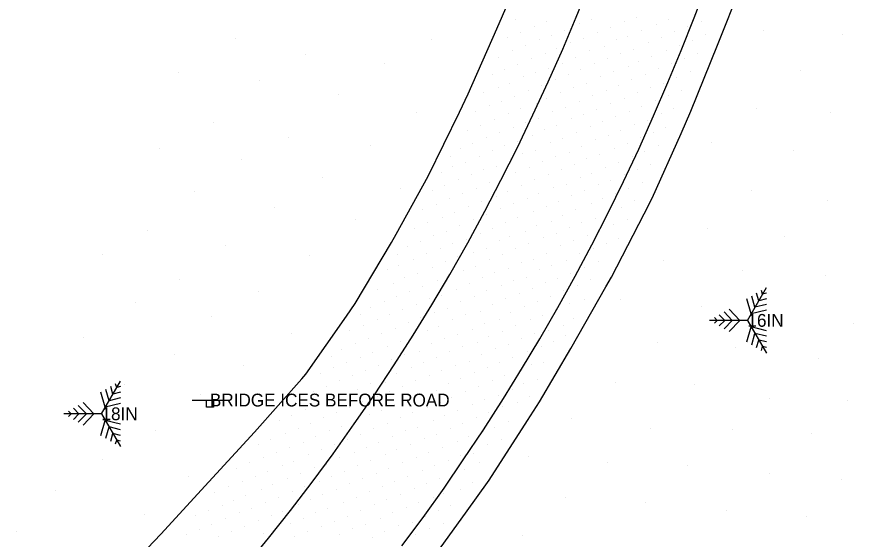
# Model space of a CAD drawing. Extents: x 1732346 to 1733076, y 467730 to 468633.
# Drawn here: x 1732514.8 to 1732632.7, y 468330.7 to 468404.1 of the extents above; entities that cross this region are included whole.
import ezdxf

# ---------------------------------------------------------------- set-up
doc = ezdxf.new("R2010")
doc.units = 0
for name, color, linetype in [('Default', 7, 'Continuous'), ('S_Ground_SpotElevation', 7, 'Continuous'), ('S_Roadway_Edge_Pavement', 7, 'Continuous'), ('S_Roadway_Painted_Lines', 7, 'Continuous'), ('S_Text', 7, 'Continuous'), ('S_Traffic_Sign_SinglePost', 7, 'Continuous'), ('S_Trees_Conifer_Pay', 7, 'Continuous')]:
    doc.layers.add(name, color=color, linetype=linetype)

# ---------------------------------------------------------------- blocks, each defined once
blk = doc.blocks.new('POINT_DISPLAY')
at = {"layer": 'Default'}
blk.add_line((0, 0), (0, 0), dxfattribs=at)

msp = doc.modelspace()

# ---------------------------------------------------------------- linework, layer by layer
at = {"layer": 'S_Roadway_Edge_Pavement'}
for points in [[(1732572.05, 468326.23), (1732577.91, 468334.33), (1732581.24, 468338.95), (1732586.63, 468347.37), (1732588.3, 468349.98), (1732592.71, 468357.46), (1732597.64, 468366.15), (1732598.42, 468367.53), (1732603.01, 468376.41), (1732604.14, 468378.61), (1732608.2, 468387.74), (1732609.59, 468390.87), (1732613.3, 468400.15), (1732616.65, 468408.55), (1732619.8, 468418.04), (1732621.97, 468424.57), (1732624.79, 468434.17), (1732627.07, 468441.93), (1732629.39, 468451.66), (1732630.3, 468455.46), (1732630.47, 468455.69), (1732632.18, 468465.54), (1732632.53, 468467.53), (1732633.87, 468477.44)], [(1732528.46, 468324.42), (1732535.06, 468331.36), (1732541.83, 468338.72), (1732548.25, 468345.7), (1732554.86, 468353.2), (1732555.43, 468353.85), (1732561.15, 468362.05), (1732562.37, 468363.81), (1732567.49, 468372.4), (1732568.16, 468373.54), (1732572.66, 468381.72), (1732577.04, 468390.71), (1732578.29, 468393.28), (1732582.29, 468402.45), (1732585.49, 468409.8)]]:
    msp.add_lwpolyline(points, dxfattribs=at)
at = {"layer": 'S_Roadway_Painted_Lines'}
for points in [[(1732547.02, 468326.92), (1732550.21, 468330.8), (1732553.3, 468334.72), (1732556.33, 468338.7), (1732559.29, 468342.69), (1732562.26, 468346.87), (1732565.09, 468350.99), (1732567.86, 468355.17), (1732570.53, 468359.36), (1732573.15, 468363.62), (1732575.67, 468367.87), (1732578.22, 468372.34), (1732580.62, 468376.82), (1732582.86, 468381.18), (1732585.19, 468385.77), (1732587.38, 468390.33), (1732589.53, 468394.98), (1732591.56, 468399.57), (1732593.46, 468404.1), (1732595.35, 468408.81)], [(1732568.94, 468329.72), (1732571.94, 468333.7), (1732574.88, 468337.82), (1732577.58, 468341.83), (1732580.42, 468346.04), (1732583.25, 468350.46), (1732585.78, 468354.58), (1732588.32, 468358.82), (1732590.88, 468363.26), (1732593.3, 468367.67), (1732595.65, 468372.08), (1732597.94, 468376.55), (1732600.12, 468380.97), (1732602.24, 468385.51), (1732604.34, 468390.2), (1732606.35, 468394.89), (1732608.21, 468399.41), (1732610.02, 468404), (1732611.86, 468408.79)]]:
    msp.add_lwpolyline(points, dxfattribs=at)
at = {"layer": 'S_Traffic_Sign_SinglePost'}
msp.add_line((1732539.47, 468350.23), (1732544.46, 468350.23), dxfattribs=at)
msp.add_lwpolyline([(1732541.46, 468350.23), (1732542.46, 468350.23), (1732542.46, 468349.23), (1732541.46, 468349.23)], close=True, dxfattribs=at)
at = {"layer": 'S_Trees_Conifer_Pay'}
for p, q in [((1732617.53, 468361.44), (1732620.19, 468366.05)), ((1732618.59, 468363.28), (1732618.14, 468364.86)), ((1732619.12, 468364.21), (1732618.82, 468365.26)), ((1732619.66, 468365.13), (1732619.5, 468365.66)), ((1732620.19, 468365.26), (1732619.66, 468365.13)), ((1732618.06, 468362.36), (1732617.45, 468364.47)), ((1732620.19, 468363.68), (1732618.59, 468363.28)), ((1732620.19, 468364.47), (1732619.12, 468364.21)), ((1732615.4, 468361.44), (1732614.26, 468362.63)), ((1732616.46, 468361.44), (1732614.94, 468363.02)), ((1732620.19, 468362.89), (1732618.06, 468362.36)), ((1732617.53, 468361.44), (1732612.2, 468361.44)), ((1732613.27, 468361.44), (1732612.89, 468361.84)), ((1732612.89, 468361.05), (1732613.27, 468361.44)), ((1732614.33, 468361.44), (1732613.57, 468362.23)), ((1732613.57, 468360.65), (1732614.33, 468361.44)), ((1732614.26, 468360.25), (1732615.4, 468361.44)), ((1732614.94, 468359.86), (1732616.46, 468361.44)), ((1732617.53, 468361.44), (1732620.19, 468356.83)), ((1732617.45, 468358.41), (1732618.06, 468360.52)), ((1732620.19, 468359.99), (1732618.06, 468360.52)), ((1732618.14, 468358.02), (1732618.59, 468359.59)), ((1732620.19, 468359.2), (1732618.59, 468359.59)), ((1732618.82, 468357.62), (1732619.12, 468358.67)), ((1732620.19, 468358.41), (1732619.12, 468358.67)), ((1732619.5, 468357.22), (1732619.66, 468357.75)), ((1732620.19, 468357.62), (1732619.66, 468357.75)), ((1732526.72, 468348.3), (1732529.38, 468352.91)), ((1732528.31, 468351.06), (1732528.01, 468352.12)), ((1732528.85, 468351.98), (1732528.7, 468352.51)), ((1732529.38, 468352.12), (1732528.85, 468351.98)), ((1732527.25, 468349.22), (1732526.64, 468351.33)), ((1732527.79, 468350.14), (1732527.33, 468351.72)), ((1732529.38, 468351.33), (1732528.31, 468351.06)), ((1732524.59, 468348.3), (1732523.45, 468349.48)), ((1732525.65, 468348.3), (1732524.13, 468349.88)), ((1732529.38, 468349.74), (1732527.25, 468349.22)), ((1732529.38, 468350.54), (1732527.79, 468350.14)), ((1732526.72, 468348.3), (1732521.4, 468348.3)), ((1732522.46, 468348.3), (1732522.08, 468348.69)), ((1732522.08, 468347.9), (1732522.46, 468348.3)), ((1732523.53, 468348.3), (1732522.77, 468349.09)), ((1732522.77, 468347.51), (1732523.53, 468348.3)), ((1732523.45, 468347.11), (1732524.59, 468348.3)), ((1732524.13, 468346.72), (1732525.65, 468348.3)), ((1732526.72, 468348.3), (1732529.38, 468343.69)), ((1732526.64, 468345.27), (1732527.25, 468347.37)), ((1732529.38, 468346.85), (1732527.25, 468347.37)), ((1732527.33, 468344.87), (1732527.79, 468346.45)), ((1732529.38, 468346.06), (1732527.79, 468346.45)), ((1732528.01, 468344.47), (1732528.31, 468345.53)), ((1732529.38, 468345.27), (1732528.31, 468345.53)), ((1732528.7, 468344.08), (1732528.85, 468344.61)), ((1732529.38, 468344.47), (1732528.85, 468344.61))]:
    msp.add_line(p, q, dxfattribs=at)

# ---------------------------------------------------------------- block references
at = {"layer": 'S_Ground_SpotElevation'}
for p in [(1732584.87, 468403.81), (1732595.67, 468403.7), (1732601.95, 468404.09), (1732606.37, 468403.77), (1732587.59, 468402.72), (1732589.34, 468403.46), (1732593.87, 468403.14), (1732598.25, 468402.63), (1732600.19, 468403.48), (1732604.69, 468403.11), (1732609.13, 468402.78), (1732611.03, 468403.42), (1732585.58, 468401.87), (1732589.96, 468401.45), (1732591.82, 468402.24), (1732596.39, 468401.99), (1732600.7, 468401.34), (1732602.59, 468402.22), (1732605.41, 468401.29), (1732607.24, 468402.01), (1732611.66, 468401.6), (1732619.72, 468402.27), (1732630.88, 468401.67), (1732545.54, 468401.12), (1732573.05, 468400.91), (1732583.8, 468401.19), (1732588.35, 468400.9), (1732592.7, 468400.51), (1732594.46, 468401.05), (1732599.06, 468400.91), (1732603.63, 468400.57), (1732607.96, 468400.14), (1732609.86, 468400.79), (1732584.56, 468399.33), (1732586.34, 468400.05), (1732589.18, 468399), (1732590.72, 468399.64), (1732595.32, 468399.39), (1732597.44, 468399.97), (1732599.73, 468398.92), (1732601.51, 468399.48), (1732606.15, 468399.44), (1732610.56, 468398.96), (1732555.44, 468398.81), (1732582.56, 468398.4), (1732587.19, 468398.3), (1732593.42, 468398.4), (1732597.92, 468398.3), (1732602.25, 468397.84), (1732604.07, 468398.5), (1732608.71, 468398.32), (1732566.47, 468397.6), (1732583.35, 468396.7), (1732585.2, 468397.42), (1732589.61, 468396.88), (1732591.49, 468397.6), (1732594.11, 468396.72), (1732596.09, 468397.53), (1732600.77, 468397.13), (1732604.99, 468396.8), (1732606.89, 468397.59), (1732624.98, 468396.63), (1732537.6, 468396.3), (1732581.7, 468396.02), (1732586.02, 468395.67), (1732587.79, 468396.31), (1732592.38, 468396.04), (1732596.92, 468395.7), (1732598.74, 468396.37), (1732603.15, 468396.05), (1732607.52, 468395.6), (1732609.49, 468396.46), (1732548.97, 468395.15), (1732582.53, 468394.22), (1732584.11, 468394.82), (1732588.64, 468394.54), (1732590.59, 468395.31), (1732594.86, 468394.75), (1732599.39, 468394.43), (1732601.21, 468395.27), (1732603.91, 468394.23), (1732605.69, 468394.75), (1732560.06, 468393.14), (1732580.46, 468393.43), (1732586.81, 468393.75), (1732591.25, 468393.44), (1732593.02, 468394.16), (1732595.78, 468393.11), (1732597.75, 468393.83), (1732602.02, 468393.46), (1732606.43, 468393.08), (1732608.19, 468393.71), (1732583.02, 468392.28), (1732584.8, 468392.92), (1732587.82, 468391.96), (1732589.28, 468392.63), (1732593.86, 468392.27), (1732598.22, 468391.9), (1732600.19, 468392.63), (1732604.61, 468392.37), (1732571.06, 468390.67), (1732579.36, 468390.76), (1732581.31, 468391.59), (1732585.66, 468391.2), (1732590.07, 468390.78), (1732591.9, 468391.32), (1732596.27, 468391.07), (1732600.96, 468390.78), (1732602.59, 468391.47), (1732607.2, 468391.23), (1732618.87, 468391.25), (1732582.03, 468389.7), (1732583.94, 468390.51), (1732588.12, 468389.8), (1732592.79, 468389.77), (1732594.46, 468390.34), (1732599.05, 468390.09), (1732603.41, 468389.55), (1732605.5, 468390.48), (1732629.23, 468390.62), (1732542.51, 468389.23), (1732580.01, 468388.87), (1732584.67, 468388.52), (1732586.3, 468389.27), (1732590.72, 468388.84), (1732595.41, 468388.67), (1732597.22, 468389.39), (1732601.66, 468388.97), (1732606.07, 468388.61), (1732553.04, 468387.14), (1732578.17, 468388.15), (1732582.72, 468387.85), (1732587.37, 468387.46), (1732589.02, 468388.22), (1732593.49, 468387.81), (1732598.03, 468387.44), (1732599.73, 468388.13), (1732602.43, 468387.18), (1732604.36, 468387.92), (1732564.47, 468385.99), (1732578.93, 468386.35), (1732580.83, 468387.09), (1732583.42, 468385.98), (1732585.24, 468386.57), (1732589.84, 468386.4), (1732591.59, 468387.06), (1732594.18, 468385.96), (1732596.16, 468386.81), (1732600.6, 468386.36), (1732604.96, 468385.98), (1732612.51, 468386.44), (1732534.91, 468385.59), (1732577.21, 468385.67), (1732581.62, 468385.28), (1732585.97, 468384.85), (1732587.71, 468385.36), (1732592.47, 468385.1), (1732596.71, 468384.79), (1732598.78, 468385.67), (1732603.07, 468385.14), (1732623.95, 468385.36), (1732546.42, 468384.12), (1732575.73, 468384.52), (1732577.83, 468383.71), (1732579.82, 468384.55), (1732584.17, 468384.14), (1732588.71, 468383.75), (1732590.59, 468384.53), (1732594.97, 468384.17), (1732599.34, 468383.7), (1732601.34, 468384.54), (1732576.03, 468383.04), (1732580.48, 468382.67), (1732582.23, 468383.14), (1732586.82, 468382.99), (1732591.38, 468382.71), (1732593.22, 468383.3), (1732597.61, 468382.97), (1732602.03, 468382.66), (1732603.86, 468383.4), (1732557.77, 468381.59), (1732574.56, 468382.17), (1732578.68, 468381.93), (1732583.05, 468381.44), (1732584.88, 468382.21), (1732587.65, 468381.22), (1732589.57, 468381.96), (1732594.04, 468381.58), (1732595.54, 468382.14), (1732600.19, 468381.94), (1732574.91, 468380.44), (1732576.9, 468381.2), (1732581.2, 468380.8), (1732585.72, 468380.47), (1732590.26, 468380.12), (1732592.06, 468380.56), (1732596.58, 468380.5), (1732598.33, 468381.17), (1732602.71, 468380.77), (1732539.85, 468379.53), (1732568.76, 468379.98), (1732573.28, 468379.66), (1732577.45, 468379.24), (1732579.37, 468379.96), (1732582.25, 468378.92), (1732583.78, 468379.57), (1732588.2, 468379.29), (1732592.76, 468378.97), (1732594.57, 468379.71), (1732598.99, 468379.24), (1732600.81, 468380.02), (1732618.06, 468379.7), (1732573.88, 468377.76), (1732575.64, 468378.55), (1732580.13, 468378.2), (1732584.65, 468377.85), (1732586.54, 468378.61), (1732590.98, 468378.17), (1732595.66, 468377.84), (1732597.19, 468378.61), (1732601.63, 468378.23), (1732628.76, 468378.25), (1732550.99, 468377.34), (1732571.82, 468376.97), (1732576.29, 468376.59), (1732578.28, 468377.48), (1732582.85, 468377.14), (1732587.49, 468376.7), (1732589.33, 468377.41), (1732593.42, 468377.06), (1732597.86, 468376.56), (1732599.82, 468377.31), (1732562.48, 468375.61), (1732574.68, 468375.97), (1732579.06, 468375.62), (1732580.83, 468376.33), (1732585.23, 468375.94), (1732590, 468375.4), (1732591.57, 468376.25), (1732596.18, 468375.77), (1732600.68, 468375.57), (1732570.77, 468374.4), (1732572.61, 468375.17), (1732577.01, 468374.73), (1732581.62, 468374.29), (1732583.53, 468375.16), (1732587.85, 468374.74), (1732592.46, 468374.54), (1732594.2, 468375.22), (1732598.67, 468374.86), (1732611.88, 468374.39), (1732533.18, 468374.04), (1732573.4, 468373.36), (1732575.19, 468373.99), (1732579.97, 468373.61), (1732584.11, 468373.22), (1732586.38, 468373.94), (1732588.82, 468373.06), (1732590.67, 468373.69), (1732595.05, 468373.37), (1732596.68, 468373.89), (1732599.46, 468372.96), (1732622.81, 468373.18), (1732544.12, 468371.92), (1732569.78, 468371.8), (1732571.55, 468372.58), (1732576.08, 468372.28), (1732578.05, 468372.86), (1732582.64, 468372.61), (1732586.7, 468372.19), (1732591.31, 468371.92), (1732593.04, 468372.61), (1732597.69, 468372.28), (1732526.85, 468370.73), (1732568.29, 468370.68), (1732572.43, 468370.79), (1732574.31, 468371.56), (1732578.96, 468371), (1732580.87, 468371.6), (1732583.14, 468370.73), (1732584.89, 468371.49), (1732589.31, 468370.8), (1732593.97, 468370.83), (1732595.89, 468371.54), (1732555.98, 468370.57), (1732570.64, 468370.03), (1732575.01, 468369.69), (1732576.8, 468370.4), (1732581.32, 468370.04), (1732585.75, 468369.61), (1732587.42, 468369.99), (1732592.15, 468369.88), (1732596.63, 468369.66), (1732605.68, 468369.89), (1732566.97, 468368.55), (1732568.52, 468369.18), (1732573.22, 468368.94), (1732577.65, 468368.43), (1732579.23, 468368.96), (1732583.96, 468368.68), (1732588.34, 468368.58), (1732589.99, 468369.13), (1732594.69, 468368.94), (1732616.79, 468368.49), (1732537.66, 468367.24), (1732569.36, 468367.4), (1732571.21, 468368.09), (1732573.89, 468367.07), (1732575.56, 468367.53), (1732580.22, 468367.45), (1732581.96, 468368.18), (1732586.47, 468367.45), (1732590.77, 468367.3), (1732592.6, 468368.06), (1732595.53, 468367.13), (1732628.48, 468367.81), (1732567.71, 468366.69), (1732571.87, 468366.22), (1732578.4, 468366.65), (1732582.99, 468366.31), (1732584.65, 468367.02), (1732587.29, 468365.99), (1732589.11, 468366.74), (1732593.62, 468366.36), (1732548.78, 468365.44), (1732565.56, 468365.82), (1732568.21, 468364.81), (1732570.03, 468365.45), (1732574.49, 468364.99), (1732576.62, 468365.76), (1732579.21, 468364.81), (1732580.9, 468365.57), (1732585.42, 468365.22), (1732589.84, 468364.86), (1732591.73, 468365.63), (1732531.5, 468363.9), (1732566.57, 468364.12), (1732570.99, 468363.71), (1732572.83, 468364.5), (1732577.15, 468364.08), (1732581.65, 468363.71), (1732583.5, 468364.48), (1732588.04, 468364.14), (1732592.45, 468363.76), (1732594.65, 468364.36), (1732599.71, 468364.42), (1732564.55, 468363.29), (1732569.08, 468362.94), (1732573.55, 468362.55), (1732575.4, 468363.07), (1732580.06, 468362.73), (1732584.17, 468362.59), (1732586.24, 468363.38), (1732590.53, 468362.99), (1732611.1, 468363.39), (1732542.14, 468361.98), (1732563.11, 468362.21), (1732565.46, 468361.5), (1732567.18, 468362.24), (1732571.61, 468361.85), (1732576.1, 468361.52), (1732577.9, 468362.24), (1732582.61, 468361.6), (1732586.97, 468361.55), (1732588.69, 468362.13), (1732593.04, 468361.76), (1732622.37, 468362.32), (1732563.5, 468360.71), (1732568.03, 468360.36), (1732569.92, 468361.14), (1732572.49, 468360.01), (1732574.1, 468360.63), (1732578.91, 468360.11), (1732580.56, 468361.03), (1732584.92, 468360.69), (1732589.54, 468360), (1732591.69, 468360.74), (1732632.44, 468360.99), (1732524.24, 468358.99), (1732553.41, 468359.53), (1732561.54, 468359.97), (1732564.28, 468358.9), (1732566.15, 468359.65), (1732570.43, 468359.23), (1732574.95, 468358.89), (1732576.72, 468359.49), (1732581.17, 468359.22), (1732583.15, 468359.86), (1732585.75, 468358.9), (1732587.64, 468359.58), (1732591.99, 468359.25), (1732562.43, 468358.13), (1732566.88, 468357.73), (1732568.75, 468358.51), (1732573.13, 468358.15), (1732577.51, 468357.71), (1732579.58, 468358.34), (1732583.92, 468358.11), (1732588.64, 468357.77), (1732590.2, 468358.42), (1732604.95, 468358.28), (1732615.88, 468357.67), (1732537.04, 468356.67), (1732560.52, 468357.39), (1732564.86, 468356.98), (1732569.35, 468356.63), (1732571.42, 468357.05), (1732575.64, 468357.01), (1732580.09, 468356.62), (1732582.11, 468357.43), (1732586.6, 468357.06), (1732559.07, 468356.37), (1732561.18, 468355.49), (1732563.11, 468356.24), (1732567.46, 468355.88), (1732572.05, 468355.52), (1732573.78, 468356.25), (1732578.41, 468355.68), (1732582.69, 468355.53), (1732584.54, 468356.19), (1732588.9, 468355.55), (1732627.46, 468356.13), (1732546.64, 468355.04), (1732559.37, 468354.79), (1732563.87, 468354.43), (1732565.66, 468355.14), (1732570.31, 468354.83), (1732574.53, 468354.39), (1732576.54, 468355.12), (1732579.16, 468354.11), (1732580.97, 468354.84), (1732585.44, 468354.45), (1732587.19, 468355.2), (1732557.56, 468353.95), (1732560.14, 468352.95), (1732561.94, 468353.63), (1732568.18, 468353.98), (1732570.93, 468352.93), (1732572.88, 468353.72), (1732577.17, 468353.29), (1732581.69, 468352.94), (1732583.43, 468353.68), (1732588.06, 468353.12), (1732529.91, 468352.41), (1732558.37, 468352.17), (1732562.76, 468351.78), (1732564.57, 468352.51), (1732566.63, 468352.74), (1732568.99, 468352.17), (1732575.54, 468352.55), (1732579.73, 468352.14), (1732584.5, 468351.78), (1732586.05, 468352.57), (1732598.93, 468352.69), (1732610.15, 468352.4), (1732540.57, 468351.07), (1732554.66, 468350.61), (1732556.46, 468351.41), (1732560.86, 468351.06), (1732565.45, 468350.72), (1732567.19, 468351.45), (1732571.74, 468351.11), (1732573.77, 468351.51), (1732575.99, 468350.65), (1732577.89, 468351.43), (1732582.48, 468350.91), (1732586.92, 468350.73), (1732557.38, 468349.6), (1732559.1, 468350.3), (1732563.45, 468349.97), (1732567.89, 468349.59), (1732569.7, 468350.3), (1732574.38, 468349.95), (1732578.85, 468349.57), (1732580.62, 468350.37), (1732585.24, 468349.89), (1732620.7, 468350.45), (1732631.56, 468350.13), (1732555.42, 468348.87), (1732559.82, 468348.44), (1732561.6, 468349.22), (1732566.02, 468348.82), (1732570.51, 468348.48), (1732572.52, 468349.18), (1732576.78, 468348.82), (1732581.18, 468348.42), (1732583.15, 468349.26), (1732523.08, 468347.58), (1732551.68, 468347.3), (1732553.46, 468348.11), (1732557.97, 468347.74), (1732564.33, 468348.14), (1732568.77, 468347.75), (1732573.33, 468347.39), (1732574.87, 468348.05), (1732579.47, 468347.75), (1732583.87, 468347.2), (1732592.8, 468347.69), (1732534.31, 468345.89), (1732554.36, 468346.25), (1732556.11, 468346.99), (1732558.79, 468345.9), (1732560.43, 468346.58), (1732562.32, 468346.92), (1732564.97, 468346.24), (1732566.92, 468347), (1732569.44, 468345.89), (1732571.19, 468346.4), (1732575.81, 468346.3), (1732577.53, 468346.97), (1732581.99, 468346.35), (1732603.85, 468346.3), (1732615.41, 468346.03), (1732550.49, 468344.72), (1732552.54, 468345.5), (1732556.81, 468345.11), (1732561.29, 468344.71), (1732563.16, 468345.4), (1732567.58, 468345.16), (1732572.15, 468344.8), (1732573.85, 468345.38), (1732578.27, 468345.12), (1732580.46, 468345.8), (1732582.91, 468344.72), (1732626.59, 468345.47), (1732548.79, 468343.94), (1732553.09, 468343.59), (1732555.18, 468344.33), (1732559.49, 468344.05), (1732563.98, 468343.61), (1732565.6, 468344.25), (1732570.14, 468343.99), (1732574.65, 468343.62), (1732576.71, 468344.4), (1732581.02, 468343.99), (1732551.32, 468342.9), (1732555.81, 468342.55), (1732557.6, 468343.28), (1732562.26, 468342.89), (1732566.59, 468342.57), (1732568.25, 468343.27), (1732572.74, 468342.89), (1732577.19, 468342.48), (1732579.08, 468342.72), (1732526.89, 468341.82), (1732547.53, 468341.4), (1732549.48, 468342.17), (1732553.65, 468341.64), (1732560.21, 468342.16), (1732564.55, 468341.75), (1732569.04, 468341.4), (1732571.06, 468342.17), (1732575.5, 468341.76), (1732579.89, 468341.45), (1732586.71, 468342.3), (1732597.9, 468341.47), (1732545.75, 468340.64), (1732549.99, 468340.23), (1732552.21, 468341.02), (1732556.61, 468340.69), (1732558.39, 468341.12), (1732560.81, 468340.25), (1732562.74, 468341.05), (1732567.11, 468340.64), (1732571.86, 468340.33), (1732573.54, 468341.09), (1732577.81, 468340.42), (1732609.08, 468340.96), (1732538.97, 468339.44), (1732546.54, 468338.8), (1732548.37, 468339.55), (1732552.84, 468339.16), (1732554.71, 468339.94), (1732557.4, 468338.83), (1732559, 468339.52), (1732563.46, 468339.2), (1732565.37, 468339.87), (1732569.71, 468339.53), (1732574.25, 468339.19), (1732576.17, 468339.65), (1732620.61, 468339.84), (1732630.78, 468339.06), (1732544.6, 468338.04), (1732549.18, 468337.7), (1732550.82, 468338.41), (1732555.26, 468338.05), (1732559.81, 468337.7), (1732561.64, 468338.45), (1732566.2, 468338.11), (1732567.97, 468338.77), (1732570.73, 468337.74), (1732572.4, 468338.47), (1732577.2, 468337.72), (1732578.92, 468338.65), (1732520.25, 468337.48), (1732542.59, 468337.23), (1732547.02, 468336.84), (1732551.55, 468336.55), (1732553.58, 468337.33), (1732557.85, 468336.92), (1732562.59, 468336.59), (1732564.44, 468337.35), (1732568.82, 468337.01), (1732573.39, 468336.46), (1732574.79, 468337.15), (1732591.98, 468336.51), (1732543.67, 468335.45), (1732545.28, 468336.13), (1732549.78, 468335.8), (1732554.43, 468335.48), (1732556.13, 468336.24), (1732560.75, 468335.85), (1732565.04, 468335.51), (1732566.84, 468336.19), (1732571.31, 468335.77), (1732575.84, 468335.45), (1732603.2, 468335.82), (1732532.71, 468334.18), (1732541.73, 468334.7), (1732546.13, 468334.35), (1732547.8, 468335.05), (1732552.19, 468334.62), (1732556.8, 468334.37), (1732558.54, 468335.03), (1732563.18, 468334.72), (1732567.69, 468334.41), (1732569.61, 468335.13), (1732574.09, 468334.69), (1732614.54, 468334.68), (1732539.93, 468333.99), (1732544.2, 468333.59), (1732548.84, 468333.23), (1732550.6, 468334), (1732553.25, 468332.9), (1732555.11, 468333.58), (1732559.45, 468333.2), (1732561.34, 468333.92), (1732565.91, 468333.61), (1732570.48, 468333.07), (1732572.21, 468333.87), (1732574.78, 468332.92), (1732625.77, 468333.87), (1732514.8, 468331.78), (1732540.46, 468332), (1732542.22, 468332.79), (1732544.95, 468331.74), (1732546.81, 468332.49), (1732551.31, 468332.15), (1732555.62, 468331.73), (1732557.58, 468332.48), (1732562.01, 468332.12), (1732563.79, 468332.75), (1732566.51, 468331.77), (1732568.45, 468332.53), (1732572.89, 468332.17), (1732538.62, 468331.3), (1732543.23, 468330.98), (1732549.53, 468331.41), (1732553.87, 468331.02), (1732560.23, 468331.39), (1732564.75, 468330.97), (1732570.83, 468331.31), (1732585.92, 468331.14)]:
    msp.add_blockref('POINT_DISPLAY', p, dxfattribs=at)

# ---------------------------------------------------------------- texts
at = {"layer": 'S_Text'}
for s, p in [('16IN', (1732617.53, 468360.54)), ('BRIDGE ICES BEFORE ROAD', (1732541.96, 468349.33)), ('18IN', (1732526.72, 468347.4))]:
    msp.add_text(s, height=1.8, dxfattribs=at).set_placement(p)

doc.saveas('drawing.dxf')
